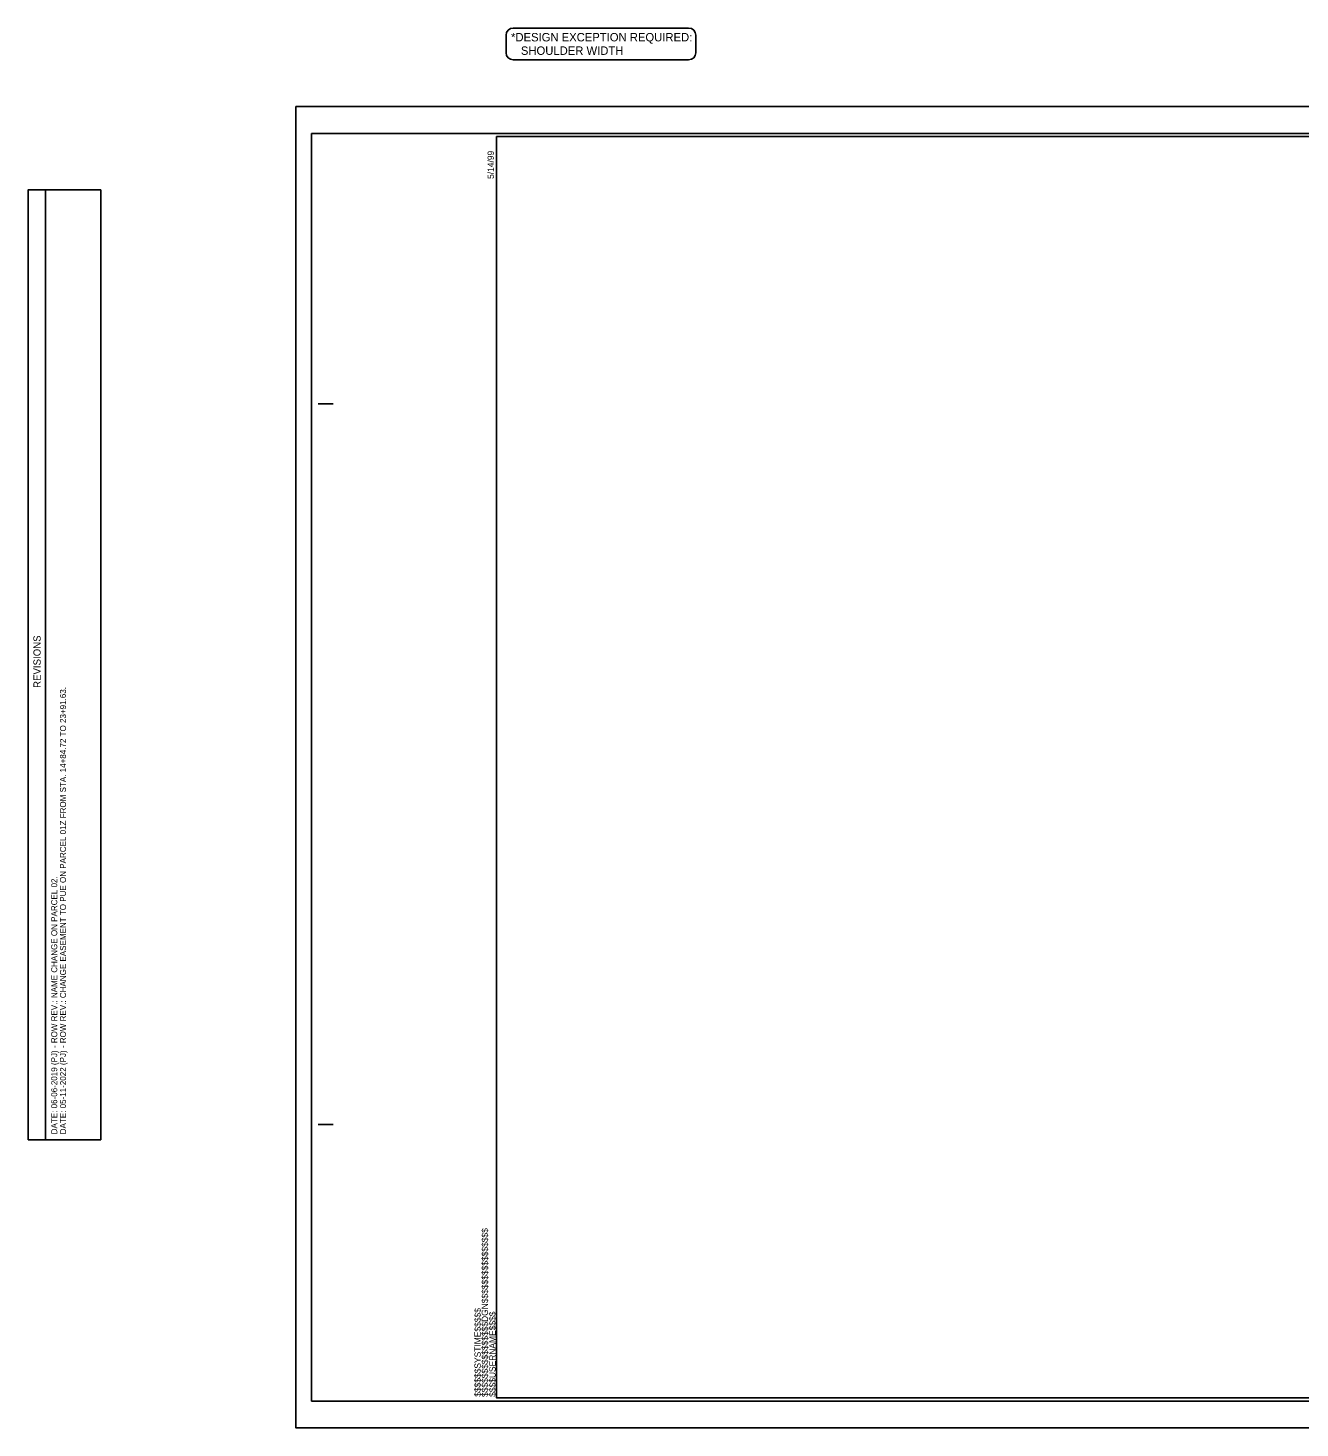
# Model space of a CAD drawing. Extents: x 1754859 to 1756977, y 736533 to 737733.
# Drawn here: x 1754859 to 1755918, y 736568 to 737733 of the extents above; entities that cross this region are included whole.
import ezdxf

# ---------------------------------------------------------------- set-up
doc = ezdxf.new("R2010")
doc.units = 0
for name, color, linetype in [('Old_Level_18', 7, 'Continuous'), ('Old_Level_38', 7, 'Continuous'), ('Scratch_Level_3', 7, 'Continuous'), ('Sheet Block Revision CELL', 7, 'Continuous'), ('Sheet Border Standard 30in CELL', 7, 'Continuous'), ('Sheet Clip Boundary CELL', 7, 'Continuous'), ('Sheet Cutting Line CELL', 7, 'Continuous'), ('Sheet Plot Border Inside CELL', 7, 'Continuous'), ('Sheet Plot Border Outside CELL', 7, 'Continuous')]:
    doc.layers.add(name, color=color, linetype=linetype)

msp = doc.modelspace()

# ---------------------------------------------------------------- linework, layer by layer
at = {"layer": 'Old_Level_18'}
for p, q in [((1755263.2, 737733.4), (1755409.2, 737733.4)), ((1755257.2, 737727.4), (1755257.2, 737712.9)), ((1755415.2, 737727.4), (1755415.2, 737712.9)), ((1755263.2, 737706.9), (1755409.2, 737706.9))]:
    msp.add_line(p, q, dxfattribs=at)
for centre, start, end in [((1755263.2, 737727.4), 90, 180), ((1755409.2, 737727.4), 0, 90), ((1755263.2, 737712.9), 180, 270), ((1755409.2, 737712.9), 270, 0)]:
    msp.add_arc(centre, 6, start, end, dxfattribs=at)
at = {"layer": 'Scratch_Level_3'}
msp.add_lwpolyline([(1755249.4, 736593), (1756749.4, 736593), (1756749.4, 737409.8), (1756549.4, 737409.8), (1756549.4, 737643), (1755249.4, 737643)], close=True, dxfattribs=at)
at = {"layer": 'Sheet Block Revision CELL'}
msp.add_line((1754873.9, 736808), (1754873.9, 737598.6), dxfattribs=at)
msp.add_lwpolyline([(1754859.4, 736808), (1754859.4, 737598.6), (1754919.9, 737598.6), (1754919.9, 736808)], close=True, dxfattribs=at)
at = {"layer": 'Sheet Border Standard 30in CELL'}
for p, q in [((1755250.4, 737643), (1755250.4, 737643)), ((1755100.9, 737420.5), (1755113.4, 737420.5)), ((1755100.9, 736820.5), (1755113.4, 736820.5))]:
    msp.add_line(p, q, dxfattribs=at)
msp.add_lwpolyline([(1756749.4, 737643), (1755249.4, 737643), (1755249.4, 736593), (1756749.4, 736593)], close=True, dxfattribs=at)
at = {"layer": 'Sheet Clip Boundary CELL'}
msp.add_lwpolyline([(1755249.4, 736593), (1756614.3, 736593), (1756747.3, 737397.4), (1756549.3, 737397.4), (1756549.4, 737643), (1755249.4, 737643)], close=True, dxfattribs=at)
msp.add_lwpolyline([(1755249.4, 736593), (1756614.3, 736593), (1756747.3, 737397.4), (1756549.3, 737397.4), (1756549.4, 737643), (1755249.4, 737643)], close=True, dxfattribs=at)
at = {"layer": 'Sheet Cutting Line CELL'}
for p, q in [((1756766.4, 737668), (1755082.4, 737668)), ((1755082.4, 737668), (1755082.4, 736568)), ((1755082.4, 736568), (1756766.4, 736568))]:
    msp.add_line(p, q, dxfattribs=at)
at = {"layer": 'Sheet Plot Border Inside CELL'}
msp.add_lwpolyline([(1756761.9, 737645.5), (1755095.4, 737645.5), (1755095.4, 736590.4), (1756761.9, 736590.4)], close=True, dxfattribs=at)
at = {"layer": 'Sheet Plot Border Outside CELL'}
msp.add_lwpolyline([(1756766.4, 737668), (1755082.4, 737668), (1755082.4, 736568), (1756766.4, 736568)], close=True, dxfattribs=at)

# ---------------------------------------------------------------- texts
at = {"layer": 'Old_Level_38'}
for s, p in [('*DESIGN EXCEPTION REQUIRED: ', (1755261.4, 737722.3)), ('SHOULDER WIDTH', (1755269.6, 737711.1))]:
    msp.add_text(s, height=7, rotation=359.995, dxfattribs=at).set_placement(p)
at = {"layer": 'Sheet Block Revision CELL'}
for s, height, p in [('REVISIONS', 6, (1754869.9, 737184.1)), ('DATE: 05-11-2022 (PJ) - ROW REV.: CHANGE EASEMENT TO PUE ON PARCEL 01Z FROM STA. 14+84.72 TO 23+91.63.', 5, (1754891, 736812.5)), ('DATE: 06-06-2019 (PJ) - ROW REV.: NAME CHANGE ON PARCEL 02.', 5, (1754883.7, 736812.5))]:
    msp.add_text(s, height=height, rotation=90, dxfattribs=at).set_placement(p)
at = {"layer": 'Sheet Border Standard 30in CELL'}
for s, p in [('5/14/99', (1755247.1, 737607.8)), ('$$$$$$$$$$$$$$$$DGN$$$$$$$$$$$$$$$$', (1755242.2, 736593.8)), ('$$$$$$SYSTIME$$$$$', (1755236.2, 736594)), ('$$$$USERNAME$$$$', (1755248.5, 736593.9))]:
    msp.add_text(s, height=5.25, rotation=90, dxfattribs=at).set_placement(p)

doc.saveas('drawing.dxf')
